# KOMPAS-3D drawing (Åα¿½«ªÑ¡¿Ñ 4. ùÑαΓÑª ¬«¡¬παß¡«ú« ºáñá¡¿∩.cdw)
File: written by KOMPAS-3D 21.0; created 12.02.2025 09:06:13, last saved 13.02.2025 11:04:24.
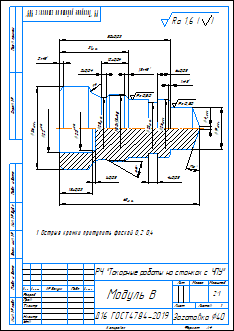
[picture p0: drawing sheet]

Sheet 1: A4, portrait

Document properties: Автор: Пользователь Windows; Знак неуказанной шероховатости: 5; Параметр неуказанной шероховатости: Ra 1,6; Полное имя файла: C:\Users\Admin\Desktop\posledniy.cdw

Title block, sheet 1: Наименование: Модуль В; designation: РЧ "Токарные работы на станках с ЧПУ"; Материал: Д16 ГОСТ4784-2019; scale: 2:1; Количество листов документа: 1; organisation: Заготовка  40; Форматы листов документа: A4; stored path: C:\Users\user\Desktop\WSR 2025\Модуль В _ Профессионалы 2025 .cdw

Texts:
  1. Острые кромки притупить фаской 0,2...0,4
  Ra 0,80
  Ra 1,6
  Ra 1,6 ( )
Dimensions and other numbers on the sheet: 36; 15; 19; 19,5; 6±0,05; 4±0,05; 50±0,03; 31; 2±0,04; 1±0,05; 12±0,04; 23; 63; -6g; 30х1,5; 26; 28; 20; 22; 1,5; 2:1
